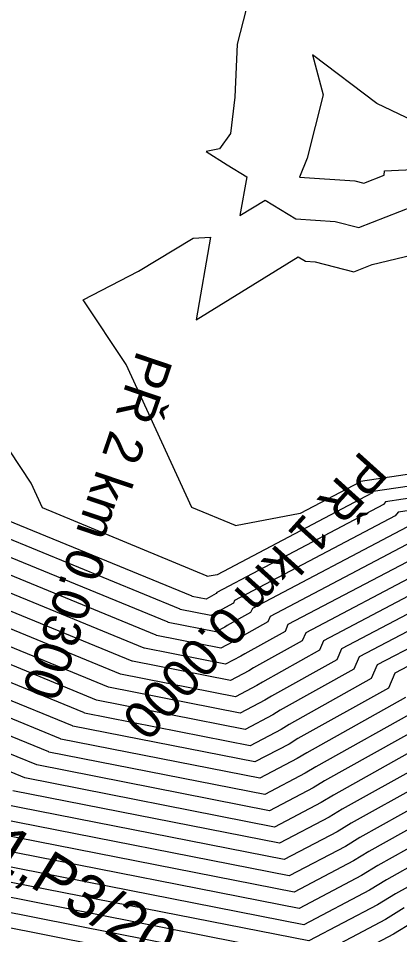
# Model space of a CAD drawing. Extents: x -549394 to -546608, y -1037055 to -1033629.
# Drawn here: x -547322.6 to -547230.9, y -1036014.3 to -1035793.8 of the extents above; entities that cross this region are included whole.
import ezdxf

# ---------------------------------------------------------------- set-up
doc = ezdxf.new("R2010")
doc.units = 0
for name, color, linetype in [('hlavni_vrst', 7, 'Continuous'), ('norm_vrst', 7, 'Continuous'), ('x_popis_pricne_rezy_C411', 7, 'Continuous'), ('x_popis_velky_C411', 7, 'Continuous')]:
    doc.layers.add(name, color=color, linetype=linetype)

msp = doc.modelspace()

# ---------------------------------------------------------------- linework, layer by layer
at = {"layer": 'hlavni_vrst'}
for p, q in [((-547251.82, -1035802.56), (-547249.25, -1035812.17)), ((-547236.37, -1035814.31), (-547251.82, -1035802.56)), ((-547249.25, -1035812.17), (-547253.15, -1035827.42)), ((-547220.11, -1035822.08), (-547236.37, -1035814.31)), ((-547253.15, -1035827.42), (-547254.99, -1035832)), ((-547254.99, -1035832), (-547241.63, -1035832.93)), ((-547239.49, -1035833.48), (-547234.56, -1035831.56)), ((-547234.56, -1035831.56), (-547234.51, -1035830.53)), ((-547234.51, -1035830.53), (-547226.01, -1035830.08)), ((-547241.63, -1035832.93), (-547239.49, -1035833.48)), ((-547191.02, -1035903.73), (-547234.27, -1035910.17)), ((-547234.76, -1035910.81), (-547274.88, -1035931.97)), ((-547234.27, -1035910.17), (-547234.76, -1035910.81)), ((-547280.8, -1035932.89), (-547325.32, -1035914.6)), ((-547220.63, -1035924.36), (-547253.44, -1035941.66)), ((-547295.17, -1035948.49), (-547331.66, -1035933.5)), ((-547280.76, -1035932.94), (-547280.8, -1035932.89)), ((-547277.43, -1035933.59), (-547280.76, -1035932.94)), ((-547276.81, -1035933.27), (-547277.43, -1035933.59)), ((-547276.65, -1035933.17), (-547276.81, -1035933.27)), ((-547275, -1035932.24), (-547276.65, -1035933.17)), ((-547274.88, -1035931.97), (-547275, -1035932.24)), ((-547206.51, -1035937.92), (-547231.99, -1035951.36)), ((-547253.44, -1035941.66), (-547254.29, -1035943.62)), ((-547254.29, -1035943.62), (-547265.99, -1035950.15)), ((-547295.14, -1035948.53), (-547295.17, -1035948.49)), ((-547271.55, -1035953.18), (-547295.14, -1035948.53)), ((-547267.14, -1035950.86), (-547271.55, -1035953.18)), ((-547265.99, -1035950.15), (-547267.14, -1035950.86)), ((-547231.99, -1035951.36), (-547233.57, -1035954.99)), ((-547309.54, -1035964.1), (-547338, -1035952.4)), ((-547233.57, -1035954.99), (-547255.34, -1035967.13)), ((-547309.51, -1035964.13), (-547309.54, -1035964.1)), ((-547265.67, -1035972.76), (-547309.51, -1035964.13)), ((-547212.86, -1035966.36), (-547244.68, -1035984.12)), ((-547257.47, -1035968.45), (-547265.67, -1035972.76)), ((-547255.34, -1035967.13), (-547257.47, -1035968.45)), ((-547192.14, -1035977.73), (-547234.02, -1036001.1)), ((-547259.78, -1035992.35), (-547323.89, -1035979.72)), ((-547244.68, -1035984.12), (-547247.8, -1035986.04)), ((-547247.8, -1035986.04), (-547259.78, -1035992.35)), ((-547253.9, -1036011.93), (-547338.27, -1035995.32)), ((-547234.02, -1036001.1), (-547238.12, -1036003.63)), ((-547238.12, -1036003.63), (-547253.9, -1036011.93))]:
    msp.add_line(p, q, dxfattribs=at)
at = {"layer": 'norm_vrst'}
for p, q in [((-547266.72, -1035787.33), (-547269.97, -1035799.98)), ((-547269.97, -1035799.98), (-547270.5, -1035812.79)), ((-547270.5, -1035812.79), (-547271.59, -1035821.51)), ((-547271.59, -1035821.51), (-547274.2, -1035825.16)), ((-547274.2, -1035825.16), (-547277.37, -1035825.83)), ((-547277.37, -1035825.83), (-547272.34, -1035829.09)), ((-547272.34, -1035829.09), (-547267.66, -1035831.93)), ((-547267.66, -1035831.93), (-547269.28, -1035841.28)), ((-547269.28, -1035841.28), (-547263.18, -1035837.53)), ((-547263.18, -1035837.53), (-547255.86, -1035842.02)), ((-547240.7, -1035844.14), (-547227.55, -1035839.03)), ((-547255.86, -1035842.02), (-547246.41, -1035842.68)), ((-547246.41, -1035842.68), (-547240.7, -1035844.14)), ((-547293.7, -1035854.68), (-547280.51, -1035846.71)), ((-547280.51, -1035846.71), (-547276.4, -1035846.42)), ((-547276.4, -1035846.42), (-547279.84, -1035866.32)), ((-547237.47, -1035853.07), (-547220.1, -1035848.82)), ((-547279.84, -1035866.32), (-547255.25, -1035851.18)), ((-547255.25, -1035851.18), (-547253.48, -1035852.27)), ((-547253.48, -1035852.27), (-547251.19, -1035852.43)), ((-547251.19, -1035852.43), (-547241.91, -1035854.8)), ((-547241.91, -1035854.8), (-547237.47, -1035853.07)), ((-547306.97, -1035861.55), (-547293.7, -1035854.68)), ((-547296.68, -1035877.13), (-547306.97, -1035861.55)), ((-547280.88, -1035911.53), (-547296.68, -1035877.13)), ((-547319.52, -1035905.63), (-547324.65, -1035897.88)), ((-547193.8, -1035898.32), (-547240.29, -1035905.23)), ((-547192.41, -1035901.02), (-547237.28, -1035907.7)), ((-547316.78, -1035911.6), (-547319.52, -1035905.63)), ((-547240.41, -1035905.39), (-547254.79, -1035912.97)), ((-547240.29, -1035905.23), (-547240.41, -1035905.39)), ((-547189.63, -1035906.44), (-547231.25, -1035912.63)), ((-547237.58, -1035908.1), (-547274.8, -1035927.72)), ((-547237.28, -1035907.7), (-547237.58, -1035908.1)), ((-547277.18, -1035928.05), (-547316.78, -1035911.6)), ((-547270.39, -1035915.88), (-547280.88, -1035911.53)), ((-547231.93, -1035913.52), (-547270.59, -1035933.91)), ((-547254.79, -1035912.97), (-547270.39, -1035915.91)), ((-547231.25, -1035912.63), (-547231.93, -1035913.52)), ((-547270.39, -1035915.91), (-547270.39, -1035915.88)), ((-547229.11, -1035916.23), (-547266.3, -1035935.85)), ((-547283.67, -1035936.01), (-547326.59, -1035918.38)), ((-547226.28, -1035918.94), (-547262.02, -1035937.79)), ((-547286.55, -1035939.13), (-547327.86, -1035922.16)), ((-547223.46, -1035921.65), (-547257.73, -1035939.72)), ((-547289.42, -1035942.25), (-547329.13, -1035925.94)), ((-547217.81, -1035927.07), (-547249.15, -1035943.6)), ((-547274.8, -1035927.72), (-547277.18, -1035928.17)), ((-547277.18, -1035928.17), (-547277.18, -1035928.05)), ((-547292.29, -1035945.37), (-547330.39, -1035929.72)), ((-547214.98, -1035929.78), (-547244.86, -1035945.54)), ((-547212.16, -1035932.49), (-547240.57, -1035947.48)), ((-547270.86, -1035934.52), (-547274.52, -1035936.56)), ((-547270.59, -1035933.91), (-547270.86, -1035934.52)), ((-547266.3, -1035935.85), (-547266.72, -1035936.79)), ((-547209.33, -1035935.21), (-547236.28, -1035949.42)), ((-547298.04, -1035951.61), (-547332.93, -1035937.28)), ((-547283.63, -1035936.06), (-547283.67, -1035936.01)), ((-547276.26, -1035937.51), (-547283.63, -1035936.06)), ((-547274.88, -1035936.78), (-547276.26, -1035937.51)), ((-547274.52, -1035936.56), (-547274.88, -1035936.78)), ((-547266.72, -1035936.79), (-547272.39, -1035939.96)), ((-547262.02, -1035937.79), (-547262.57, -1035939.07)), ((-547286.51, -1035939.18), (-547286.55, -1035939.13)), ((-547275.08, -1035941.43), (-547286.51, -1035939.18)), ((-547272.94, -1035940.3), (-547275.08, -1035941.43)), ((-547272.39, -1035939.96), (-547272.94, -1035940.3)), ((-547262.57, -1035939.07), (-547270.26, -1035943.36)), ((-547257.73, -1035939.72), (-547258.43, -1035941.34)), ((-547300.92, -1035954.73), (-547334.2, -1035941.06)), ((-547289.38, -1035942.3), (-547289.42, -1035942.25)), ((-547273.9, -1035945.34), (-547289.38, -1035942.3)), ((-547258.43, -1035941.34), (-547268.13, -1035946.75)), ((-547271.01, -1035943.82), (-547273.9, -1035945.34)), ((-547270.26, -1035943.36), (-547271.01, -1035943.82)), ((-547249.15, -1035943.6), (-547250.14, -1035945.89)), ((-547303.79, -1035957.86), (-547335.47, -1035944.84)), ((-547292.26, -1035945.41), (-547292.29, -1035945.37)), ((-547272.73, -1035949.26), (-547292.26, -1035945.41)), ((-547268.13, -1035946.75), (-547269.08, -1035947.34)), ((-547250.14, -1035945.89), (-547263.86, -1035953.55)), ((-547244.86, -1035945.54), (-547246, -1035948.16)), ((-547306.67, -1035960.98), (-547336.73, -1035948.62)), ((-547269.08, -1035947.34), (-547272.73, -1035949.26)), ((-547246, -1035948.16), (-547261.73, -1035956.94)), ((-547240.57, -1035947.48), (-547241.86, -1035950.44)), ((-547241.86, -1035950.44), (-547259.6, -1035960.34)), ((-547236.28, -1035949.42), (-547237.71, -1035952.71)), ((-547298.01, -1035951.65), (-547298.04, -1035951.61)), ((-547270.37, -1035957.09), (-547298.01, -1035951.65)), ((-547263.86, -1035953.55), (-547265.21, -1035954.37)), ((-547237.71, -1035952.71), (-547257.47, -1035963.74)), ((-547300.89, -1035954.77), (-547300.92, -1035954.73)), ((-547269.2, -1035961.01), (-547300.89, -1035954.77)), ((-547265.21, -1035954.37), (-547270.37, -1035957.09)), ((-547312.41, -1035967.22), (-547339.27, -1035956.19)), ((-547303.76, -1035957.89), (-547303.79, -1035957.86)), ((-547268.02, -1035964.93), (-547303.76, -1035957.89)), ((-547263.27, -1035957.89), (-547269.2, -1035961.01)), ((-547261.73, -1035956.94), (-547263.27, -1035957.89)), ((-547229.43, -1035957.26), (-547253.2, -1035970.53)), ((-547315.29, -1035970.34), (-547340.54, -1035959.97)), ((-547225.29, -1035959.54), (-547251.07, -1035973.93)), ((-547306.64, -1035961.01), (-547306.67, -1035960.98)), ((-547266.84, -1035968.85), (-547306.64, -1035961.01)), ((-547261.34, -1035961.41), (-547268.02, -1035964.93)), ((-547259.6, -1035960.34), (-547261.34, -1035961.41)), ((-547221.14, -1035961.81), (-547248.94, -1035977.32)), ((-547318.16, -1035973.46), (-547341.81, -1035963.75)), ((-547257.47, -1035963.74), (-547259.4, -1035964.93)), ((-547217, -1035964.08), (-547246.81, -1035980.72)), ((-547259.4, -1035964.93), (-547266.84, -1035968.85)), ((-547321.04, -1035976.58), (-547343.07, -1035967.53)), ((-547312.39, -1035967.25), (-547312.41, -1035967.22)), ((-547264.49, -1035976.68), (-547312.39, -1035967.25)), ((-547208.71, -1035968.63), (-547242.55, -1035987.51)), ((-547315.27, -1035970.37), (-547315.29, -1035970.34)), ((-547263.31, -1035980.6), (-547315.27, -1035970.37)), ((-547253.2, -1035970.53), (-547255.53, -1035971.97)), ((-547204.57, -1035970.91), (-547240.42, -1035990.91)), ((-547255.53, -1035971.97), (-547264.49, -1035976.68)), ((-547200.43, -1035973.18), (-547238.28, -1035994.31)), ((-547318.14, -1035973.49), (-547318.16, -1035973.46)), ((-547262.14, -1035984.51), (-547318.14, -1035973.49)), ((-547253.6, -1035975.48), (-547263.31, -1035980.6)), ((-547251.07, -1035973.93), (-547253.6, -1035975.48)), ((-547196.28, -1035975.46), (-547236.15, -1035997.7)), ((-547321.02, -1035976.61), (-547321.04, -1035976.58)), ((-547260.96, -1035988.43), (-547321.02, -1035976.61)), ((-547248.94, -1035977.32), (-547251.66, -1035979)), ((-547251.66, -1035979), (-547262.14, -1035984.51)), ((-547188, -1035980), (-547231.89, -1036004.5)), ((-547246.81, -1035980.72), (-547249.73, -1035982.52)), ((-547258.61, -1035996.27), (-547326.77, -1035982.84)), ((-547249.73, -1035982.52), (-547260.96, -1035988.43)), ((-547257.43, -1036000.18), (-547329.64, -1035985.96)), ((-547242.55, -1035987.51), (-547245.86, -1035989.56)), ((-547256.25, -1036004.1), (-547332.52, -1035989.08)), ((-547245.86, -1035989.56), (-547258.61, -1035996.27)), ((-547240.42, -1035990.91), (-547243.93, -1035993.08)), ((-547255.07, -1036008.02), (-547335.39, -1035992.2)), ((-547243.93, -1035993.08), (-547257.43, -1036000.18)), ((-547238.28, -1035994.31), (-547241.99, -1035996.59)), ((-547241.99, -1035996.59), (-547256.25, -1036004.1)), ((-547252.72, -1036015.85), (-547341.15, -1035998.44)), ((-547236.15, -1035997.7), (-547240.06, -1036000.11)), ((-547251.54, -1036019.77), (-547344.02, -1036001.56)), ((-547240.06, -1036000.11), (-547255.07, -1036008.02)), ((-547250.37, -1036023.69), (-547346.9, -1036004.68)), ((-547231.89, -1036004.5), (-547236.19, -1036007.15)), ((-547249.19, -1036027.6), (-547349.77, -1036007.8)), ((-547236.19, -1036007.15), (-547252.72, -1036015.85)), ((-547229.76, -1036007.89), (-547234.25, -1036010.67)), ((-547234.25, -1036010.67), (-547251.54, -1036019.77)), ((-547227.63, -1036011.29), (-547232.32, -1036014.19)), ((-547232.32, -1036014.19), (-547250.37, -1036023.69))]:
    msp.add_line(p, q, dxfattribs=at)

# ---------------------------------------------------------------- texts
at = {"layer": 'x_popis_pricne_rezy_C411'}
for s, rotation, p in [('PŘ 2 km 0.0300', 251.2916, (-547293.91, -1035873.43)), ('PŘ 1 km 0.0000', 227.9685, (-547240.01, -1035897.55))]:
    msp.add_text(s, height=9.0627, rotation=rotation, dxfattribs=at).set_placement(p)
at = {"layer": 'x_popis_velky_C411'}
msp.add_text('C411,P3/20', height=10.5, rotation=328.2284, dxfattribs=at).set_placement((-547352.04, -1035982.85))

doc.saveas('drawing.dxf')
